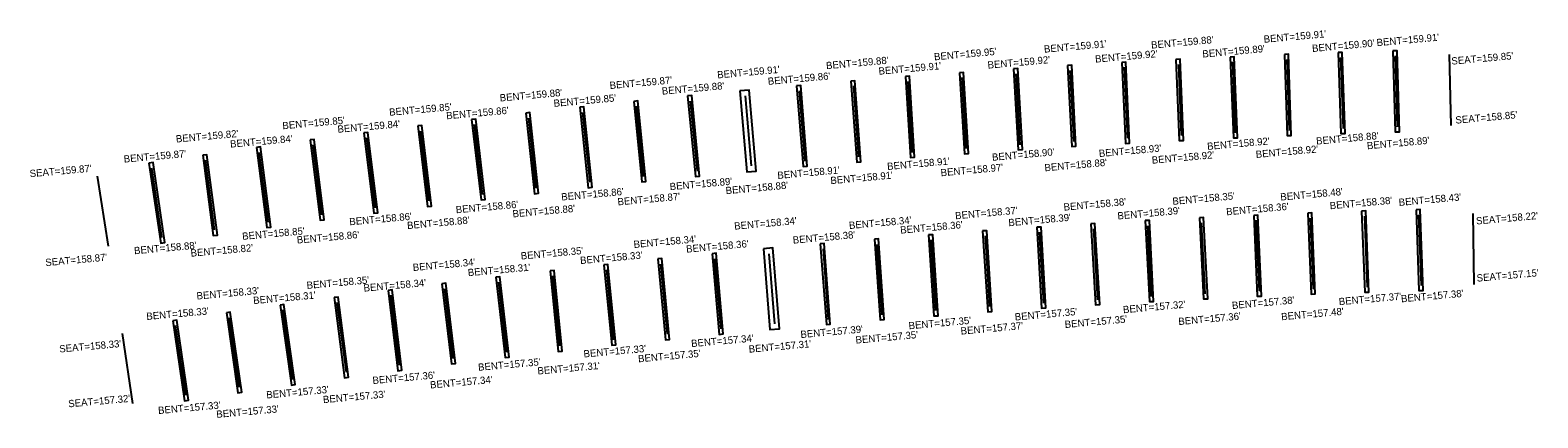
# Model space of a CAD drawing. Extents: x 2107167 to 2121551, y 865392 to 868477.
# Drawn here: x 2114613 to 2115449, y 868262 to 868477 of the extents above; entities that cross this region are included whole.
import ezdxf

# ---------------------------------------------------------------- set-up
doc = ezdxf.new("R2010")
doc.units = 0
for name, color, linetype in [('RD_EX_Bridge', 7, 'Continuous'), ('RD_EX_Bridge_txCode', 7, 'Continuous'), ('RD_EX_Conc', 7, 'Continuous')]:
    doc.layers.add(name, color=color, linetype=linetype)

msp = doc.modelspace()

# ---------------------------------------------------------------- linework, layer by layer
at = {"layer": 'RD_EX_Bridge'}
for p, q in [((2115399.86, 868463.12), (2115400.69, 868423.82)), ((2115219.58, 868456.11), (2115221.34, 868416.78)), ((2115249.62, 868457.7), (2115251.18, 868418.29)), ((2115279.59, 868459.08), (2115281.17, 868419.8)), ((2115309.68, 868460.44), (2115311.08, 868421.06)), ((2115339.6, 868461.48), (2115340.95, 868422.14)), ((2115369.92, 868462.49), (2115371.01, 868423.1)), ((2115099.55, 868448.11), (2115101.98, 868408.83)), ((2115129.48, 868450.37), (2115131.91, 868410.97)), ((2115159.44, 868452.38), (2115161.72, 868413.06)), ((2115189.44, 868454.28), (2115191.54, 868414.92)), ((2115009.21, 868440.21), (2115012.54, 868401.39)), ((2115039.18, 868443.03), (2115042.34, 868404.07)), ((2115069.32, 868445.81), (2115072.15, 868406.48)), ((2114919.02, 868431.03), (2114923.08, 868392.37)), ((2114948.89, 868434.44), (2114952.78, 868395.49)), ((2114978.79, 868437.34), (2114982.58, 868398.52)), ((2114859.02, 868424.36), (2114863.49, 868385.55)), ((2114889.08, 868427.86), (2114893.16, 868389.11)), ((2114769.53, 868413.07), (2114774.29, 868374.23)), ((2114799.3, 868416.89), (2114804.06, 868378.22)), ((2114829.18, 868420.72), (2114833.73, 868381.94)), ((2114709.76, 868404.66), (2114714.81, 868366.03)), ((2114739.61, 868408.82), (2114744.58, 868370.26)), ((2114679.97, 868400.2), (2114685.56, 868361.75)), ((2114649.91, 868395.74), (2114655.89, 868356.97)), ((2115292.59, 868371.22), (2115294.42, 868331.92)), ((2115322.68, 868372.38), (2115324.39, 868333.12)), ((2115352.83, 868373.48), (2115354.41, 868334.12)), ((2115382.86, 868374.34), (2115384.19, 868335.07)), ((2115412.94, 868375.04), (2115413.42, 868335.66)), ((2115172.42, 868364.64), (2115174.76, 868325.34)), ((2115202.47, 868366.48), (2115204.69, 868327.2)), ((2115232.5, 868368.2), (2115234.54, 868328.95)), ((2115264.46, 868330.46), (2115262.5, 868369.75)), ((2115052.52, 868355.36), (2115055.38, 868316.27)), ((2115082.26, 868357.72), (2115085.1, 868318.74)), ((2115112.35, 868360.44), (2115114.95, 868321.16)), ((2115142.42, 868362.63), (2115144.76, 868323.35)), ((2114962.28, 868346.88), (2114965.94, 868308.09)), ((2114992.32, 868349.84), (2114995.71, 868311.08)), ((2115022.41, 868352.62), (2115025.6, 868313.86)), ((2114902.41, 868340.44), (2114906.34, 868301.63)), ((2114932.34, 868343.71), (2114936.16, 868304.88)), ((2114812.63, 868329.65), (2114817.45, 868290.96)), ((2114842.49, 868333.3), (2114847.17, 868294.6)), ((2114872.38, 868336.96), (2114876.86, 868298.1)), ((2114752.9, 868321.61), (2114758.28, 868282.94)), ((2114782.86, 868325.65), (2114787.88, 868286.97)), ((2114693.18, 868312.82), (2114698.88, 868274.24)), ((2114722.97, 868317.07), (2114728.45, 868278.69)), ((2114663.72, 868308.38), (2114669.48, 868269.63))]:
    msp.add_line(p, q, dxfattribs=at)
at = {"layer": 'RD_EX_Conc'}
for points in [[(2115308.39, 868463.2), (2115309.95, 868418.24), (2115312.25, 868418.33), (2115310.68, 868463.28)], [(2115338.18, 868464.26), (2115339.68, 868419.3), (2115342.04, 868419.38), (2115340.53, 868464.34)], [(2115368.55, 868465.21), (2115369.84, 868420.29), (2115372.2, 868420.36), (2115370.91, 868465.28)], [(2115158.16, 868455.23), (2115160.75, 868410.37), (2115163.06, 868410.5), (2115160.47, 868455.37)], [(2115188.13, 868457.15), (2115190.52, 868412.22), (2115192.81, 868412.35), (2115190.42, 868457.27)], [(2115218.2, 868458.82), (2115220.22, 868413.84), (2115222.47, 868413.95), (2115220.44, 868458.92)], [(2115248.22, 868460.4), (2115250.12, 868415.47), (2115252.43, 868415.57), (2115250.53, 868460.5)], [(2115278.29, 868461.78), (2115280.1, 868416.91), (2115282.37, 868417), (2115280.56, 868461.87)], [(2115067.91, 868448.36), (2115071.22, 868403.52), (2115073.53, 868403.69), (2115070.22, 868448.53)], [(2115098.18, 868450.98), (2115100.97, 868406.09), (2115103.22, 868406.23), (2115100.43, 868451.12)], [(2115128.12, 868452.98), (2115130.89, 868408.13), (2115133.15, 868408.27), (2115130.38, 868453.12)], [(2114977.39, 868440.2), (2114981.74, 868395.5), (2114984.03, 868395.73), (2114979.68, 868440.42)], [(2115006.31, 868442.96), (2115010.23, 868398.09), (2115015.47, 868398.55), (2115011.55, 868443.41)], [(2115037.85, 868445.84), (2115041.43, 868401.05), (2115043.72, 868401.23), (2115040.14, 868446.02)], [(2114887.57, 868430.67), (2114892.46, 868385.99), (2114894.74, 868386.24), (2114889.85, 868430.92)], [(2114917.54, 868433.97), (2114922.24, 868389.3), (2114924.49, 868389.54), (2114919.79, 868434.21)], [(2114947.48, 868437.17), (2114951.97, 868392.49), (2114954.27, 868392.72), (2114949.79, 868437.4)], [(2114827.67, 868423.53), (2114833.03, 868378.88), (2114835.28, 868379.15), (2114829.91, 868423.8)], [(2114857.58, 868427.14), (2114862.78, 868382.51), (2114865.05, 868382.78), (2114859.84, 868427.4)], [(2114767.97, 868415.78), (2114773.6, 868371.25), (2114775.85, 868371.54), (2114770.22, 868416.06)], [(2114797.76, 868419.73), (2114803.33, 868375.15), (2114805.59, 868375.43), (2114800.02, 868420.01)], [(2114708.38, 868407.28), (2114714.28, 868362.77), (2114716.57, 868363.07), (2114710.66, 868407.58)], [(2114738.18, 868411.64), (2114743.9, 868367.19), (2114746.18, 868367.49), (2114740.46, 868411.93)], [(2114678.58, 868402.98), (2114685.1, 868358.6), (2114687.35, 868358.93), (2114680.82, 868403.31)], [(2115231.27, 868371.06), (2115233.53, 868326.14), (2115235.85, 868326.26), (2115233.58, 868371.18)], [(2115261.25, 868372.64), (2115263.53, 868327.62), (2115265.86, 868327.74), (2115263.58, 868372.76)], [(2115291.38, 868373.95), (2115293.35, 868329.11), (2115295.68, 868329.21), (2115293.7, 868374.05)], [(2115321.44, 868375.23), (2115323.31, 868330.33), (2115325.55, 868330.42), (2115323.69, 868375.32)], [(2115351.25, 868376.3), (2115353.05, 868331.35), (2115355.32, 868331.44), (2115353.51, 868376.39)], [(2115381.44, 868377.07), (2115383.07, 868332.24), (2115385.41, 868332.32), (2115383.78, 868377.16)], [(2115110.99, 868363.1), (2115114.02, 868318.18), (2115116.36, 868318.34), (2115113.32, 868363.25)], [(2115141.04, 868365.3), (2115143.87, 868320.51), (2115146.18, 868320.66), (2115143.35, 868365.44)], [(2115171.09, 868367.37), (2115173.76, 868322.49), (2115176.1, 868322.63), (2115173.43, 868367.51)], [(2115201.02, 868369.3), (2115203.68, 868324.35), (2115205.96, 868324.49), (2115203.3, 868369.44)], [(2115019.44, 868355.46), (2115023.04, 868310.68), (2115028.32, 868311.1), (2115024.72, 868355.88)], [(2115050.99, 868358.23), (2115054.33, 868313.49), (2115056.52, 868313.65), (2115053.18, 868358.39)], [(2115080.97, 868360.74), (2115084.15, 868315.98), (2115086.44, 868316.14), (2115083.25, 868360.9)], [(2114930.97, 868346.55), (2114935.35, 868301.91), (2114937.58, 868302.12), (2114933.2, 868346.77)], [(2114960.83, 868349.78), (2114965.1, 868305), (2114967.36, 868305.21), (2114963.09, 868349.99)], [(2114990.97, 868352.72), (2114994.93, 868307.99), (2114997.18, 868308.19), (2114993.23, 868352.92)], [(2114870.97, 868339.7), (2114876.14, 868295.08), (2114878.38, 868295.34), (2114873.21, 868339.96)], [(2114901.05, 868343.23), (2114905.54, 868298.52), (2114907.82, 868298.75), (2114903.33, 868343.46)], [(2114811.19, 868332.36), (2114816.68, 868287.81), (2114818.94, 868288.09), (2114813.45, 868332.64)], [(2114841.04, 868336.08), (2114846.43, 868291.57), (2114848.67, 868291.84), (2114843.28, 868336.35)], [(2114751.29, 868324.23), (2114757.56, 868279.81), (2114759.75, 868280.12), (2114753.48, 868324.54)], [(2114781.31, 868328.34), (2114787.06, 868283.85), (2114789.34, 868284.15), (2114783.59, 868328.63)], [(2114691.75, 868315.56), (2114698.33, 868271.17), (2114700.57, 868271.51), (2114693.99, 868315.9)], [(2114721.5, 868319.99), (2114727.89, 868275.57), (2114730.1, 868275.88), (2114723.7, 868320.31)]]:
    msp.add_lwpolyline(points, close=True, dxfattribs=at)

# ---------------------------------------------------------------- texts
at = {"layer": 'RD_EX_Bridge_txCode'}
for s, p in [("BENT=159.88'", (2115234.64, 868466.4)), ("BENT=159.91'", (2115297.09, 868469.64)), ("BENT=159.90'", (2115323.91, 868464.54)), ("BENT=159.91'", (2115359.73, 868467.78)), ("BENT=159.95'", (2115114.22, 868459.89)), ("BENT=159.91'", (2115175.21, 868464.14)), ("BENT=159.92'", (2115203.58, 868458.64)), ("BENT=159.89'", (2115263.09, 868461.45)), ("SEAT=159.85'", (2115401.22, 868457.52)), ("BENT=159.91'", (2114993.96, 868449.89)), ("BENT=159.88'", (2115054.34, 868455.01)), ("BENT=159.91'", (2115083.47, 868451.93)), ("BENT=159.92'", (2115143.93, 868455.31)), ("BENT=159.87'", (2114934.29, 868444)), ("BENT=159.88'", (2114963.24, 868440.87)), ("BENT=159.86'", (2115022.04, 868446.31)), ("BENT=159.88'", (2114873.33, 868437.09)), ("BENT=159.85'", (2114903.22, 868434.1)), ("BENT=159.85'", (2114812, 868429.17)), ("BENT=159.86'", (2114843.64, 868427.23)), ("SEAT=158.85'", (2115403.47, 868424.79)), ("BENT=159.82'", (2114693.69, 868414.36)), ("BENT=159.85'", (2114752.76, 868421.69)), ("BENT=159.84'", (2114783.34, 868419.74)), ("BENT=159.84'", (2114723.76, 868411.51)), ("BENT=158.93'", (2115205.67, 868406.3)), ("BENT=158.92'", (2115265.74, 868410.24)), ("BENT=158.88'", (2115326.19, 868413.18)), ("BENT=158.89'", (2115354.35, 868410.58)), ("BENT=159.87'", (2114664.76, 868403.21)), ("BENT=158.91'", (2115088.21, 868399.11)), ("BENT=158.90'", (2115146.39, 868404.19)), ("BENT=158.88'", (2115175.51, 868398.37)), ("BENT=158.92'", (2115235.02, 868402.57)), ("BENT=158.92'", (2115292.7, 868405.79)), ("SEAT=159.87'", (2114612.57, 868395.12)), ("BENT=158.91'", (2115027.34, 868394.14)), ("BENT=158.91'", (2115056.76, 868391.27)), ("BENT=158.97'", (2115117.89, 868395.62)), ("BENT=158.86'", (2114907.45, 868382.19)), ("BENT=158.89'", (2114967.61, 868387.9)), ("BENT=158.88'", (2114998.64, 868385.7)), ("BENT=158.48'", (2115306.32, 868382.15)), ("BENT=158.86'", (2114848.95, 868375.1)), ("BENT=158.88'", (2114880.43, 868372.81)), ("BENT=158.87'", (2114938.68, 868379.48)), ("BENT=158.38'", (2115186.11, 868376.54)), ("BENT=158.35'", (2115246.48, 868379.78)), ("BENT=158.36'", (2115276.3, 868373.97)), ("BENT=158.38'", (2115333.74, 868377.32)), ("BENT=158.43'", (2115371.99, 868379.18)), ("BENT=158.86'", (2114789.89, 868368.44)), ("BENT=158.88'", (2114821.92, 868366.33)), ("BENT=158.34'", (2115003.39, 868366.01)), ("BENT=158.34'", (2115067.04, 868366.37)), ("BENT=158.37'", (2115125.94, 868371.77)), ("BENT=158.39'", (2115155.49, 868367.92)), ("BENT=158.39'", (2115215.99, 868371.66)), ("SEAT=158.22'", (2115414.9, 868368.88)), ("BENT=158.85'", (2114730.46, 868360.37)), ("BENT=158.86'", (2114760.77, 868358.32)), ("BENT=158.34'", (2114947.59, 868355.84)), ("BENT=158.38'", (2115035.88, 868358.25)), ("BENT=158.36'", (2115095.48, 868363.8)), ("BENT=158.88'", (2114670.47, 868352.39)), ("BENT=158.82'", (2114701.85, 868351.01)), ("BENT=158.35'", (2114885, 868349.46)), ("BENT=158.36'", (2114976.73, 868353.27)), ("SEAT=158.87'", (2114621.25, 868345.81)), ("BENT=158.34'", (2114825.09, 868343.08)), ("BENT=158.31'", (2114855.63, 868340.23)), ("BENT=158.33'", (2114917.9, 868346.95)), ("BENT=158.35'", (2114766.21, 868333.15)), ("BENT=158.34'", (2114797.8, 868331.65)), ("SEAT=157.15'", (2115415.23, 868337.17)), ("BENT=158.33'", (2114705.16, 868327.28)), ("BENT=158.31'", (2114736.59, 868324.76)), ("BENT=157.37'", (2115338.76, 868324.13)), ("BENT=157.38'", (2115373.25, 868325.72)), ("BENT=158.33'", (2114677.3, 868315.94)), ("BENT=157.35'", (2115159.02, 868315.63)), ("BENT=157.32'", (2115219.04, 868319.67)), ("BENT=157.38'", (2115279.48, 868322)), ("BENT=157.48'", (2115306.81, 868315.78)), ("BENT=157.39'", (2115040.15, 868305.91)), ("BENT=157.35'", (2115100.13, 868310.77)), ("BENT=157.37'", (2115128.99, 868307.82)), ("BENT=157.35'", (2115186.71, 868311.46)), ("BENT=157.36'", (2115249.76, 868313.11)), ("SEAT=158.33'", (2114628.98, 868297.9)), ("BENT=157.34'", (2114979.5, 868300.9)), ("BENT=157.31'", (2115011.43, 868297.77)), ("BENT=157.35'", (2115070.7, 868302.83)), ("BENT=157.33'", (2114919.82, 868295.14)), ("BENT=157.35'", (2114950.05, 868292.45)), ("BENT=157.36'", (2114802.76, 868280.42)), ("BENT=157.35'", (2114861.32, 868287.74)), ("BENT=157.31'", (2114894.26, 868285.7)), ("BENT=157.33'", (2114743.84, 868272.41)), ("BENT=157.34'", (2114834.68, 868277.93)), ("SEAT=157.32'", (2114633.97, 868267.48)), ("BENT=157.33'", (2114683.8, 868263.77)), ("BENT=157.33'", (2114775.27, 868269.81)), ("BENT=157.33'", (2114716.11, 868261.65))]:
    msp.add_text(s, height=4, rotation=5.07046, dxfattribs=at).set_placement(p)

doc.saveas('drawing.dxf')
